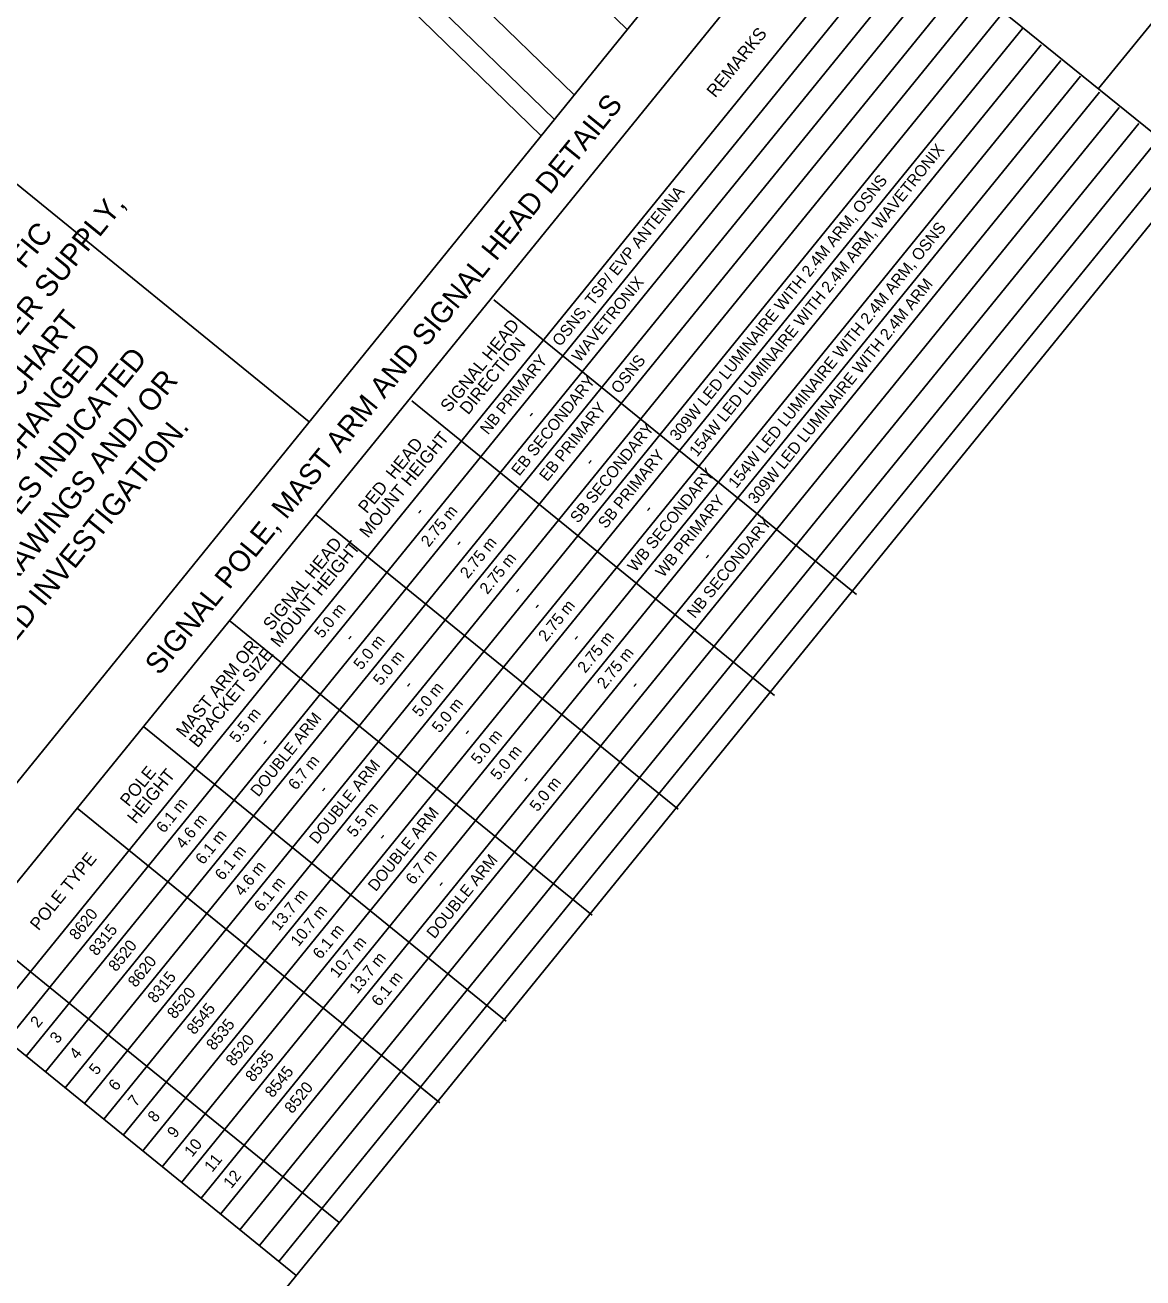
# Model space of a CAD drawing. Extents: x 592613 to 600223, y 4837996 to 4840103.
# Drawn here: x 592777.5 to 592830.8, y 4838919.8 to 4838979.6 of the extents above; entities that cross this region are included whole.
import ezdxf

# ---------------------------------------------------------------- set-up
doc = ezdxf.new("R2010")
doc.units = 0
for name, color, linetype in [('ENG_BORDER', 7, 'Continuous'), ('ENG_KILLSTRIP', 7, 'Continuous'), ('ENG_SIDEWALK', 7, 'Continuous'), ('ENG_TITLEBLOCK', 7, 'Continuous'), ('ENG_TX_TITLEBLOCK', 7, 'Continuous'), ('Level 31', 7, 'Continuous'), ('Level 54', 7, 'Continuous'), ('ROW_ENG_ROW', 7, 'Continuous')]:
    doc.layers.add(name, color=color, linetype=linetype)

msp = doc.modelspace()

# ---------------------------------------------------------------- linework, layer by layer
at = {"layer": 'ENG_BORDER'}
for p, q in [((592790.401, 4838919.927), (592686.018, 4839004.737)), ((592833.5, 4838972.733), (592813.742, 4838988.708)), ((592773.181, 4838933.919), (592816.128, 4838986.778)), ((592799.688, 4838966.543), (592799.798, 4838966.679))]:
    msp.add_line(p, q, dxfattribs=at)
msp.add_lwpolyline([(592762.862, 4838886.033), (592888.241, 4839040.345), (592783.858, 4839125.156)], dxfattribs=at)
at = {"layer": 'ENG_KILLSTRIP'}
msp.add_line((592806.215, 4838979.424), (592802.069, 4838983.452), dxfattribs=at)
at = {"layer": 'ENG_SIDEWALK'}
for p, q in [((592803.686, 4838976.304), (592781.61, 4838997.751)), ((592802.738, 4838975.135), (592780.976, 4838996.276))]:
    msp.add_line(p, q, dxfattribs=at)
at = {"layer": 'ENG_TITLEBLOCK'}
for p, q in [((592770.854, 4838935.809), (592843.567, 4839025.495)), ((592828.718, 4838976.602), (592839.517, 4838989.892)), ((592791.029, 4838960.693), (592772.408, 4838975.825))]:
    msp.add_line(p, q, dxfattribs=at)
at = {"layer": 'Level 31'}
for p, q in [((592775.654, 4838931.909), (592818.581, 4838984.742)), ((592778.657, 4838933.708), (592819.509, 4838983.988)), ((592777.511, 4838930.4), (592820.437, 4838983.234)), ((592778.439, 4838929.646), (592821.338, 4838982.446)), ((592779.367, 4838928.893), (592822.28, 4838981.709)), ((592780.295, 4838928.139), (592823.222, 4838980.971)), ((592781.222, 4838927.385), (592824.135, 4838980.201)), ((592782.15, 4838926.631), (592825.091, 4838979.48)), ((592783.079, 4838925.877), (592825.992, 4838978.692)), ((592784.007, 4838925.122), (592826.92, 4838977.939)), ((592784.935, 4838924.368), (592827.862, 4838977.201)), ((592785.863, 4838923.615), (592828.776, 4838976.43)), ((592786.791, 4838922.86), (592829.718, 4838975.694)), ((592787.719, 4838922.106), (592830.646, 4838974.939)), ((592788.648, 4838921.352), (592831.573, 4838974.186)), ((592789.575, 4838920.598), (592832.502, 4838973.431)), ((592817.174, 4838952.449), (592799.851, 4838966.523)), ((592813.248, 4838947.618), (592795.926, 4838961.692)), ((592808.656, 4838942.186), (592791.333, 4838956.26)), ((592787.26, 4838951.169), (592787.222, 4838951.2)), ((592804.545, 4838937.126), (592787.26, 4838951.169)), ((592783.126, 4838946.129), (592783.111, 4838946.141)), ((592800.433, 4838932.066), (592783.126, 4838946.129)), ((592797.271, 4838928.174), (592779.949, 4838942.248)), ((592776.582, 4838931.155), (592778.604, 4838933.643))]:
    msp.add_line(p, q, dxfattribs=at)
at = {"layer": 'Level 54'}
for p, q in [((592797.169, 4838928.257), (592779.949, 4838942.248)), ((592777.701, 4838934.439), (592775.233, 4838936.445)), ((592777.706, 4838934.435), (592777.701, 4838934.439)), ((592778.634, 4838933.681), (592777.706, 4838934.435)), ((592792.453, 4838922.453), (592778.634, 4838933.681))]:
    msp.add_line(p, q, dxfattribs=at)
at = {"layer": 'ROW_ENG_ROW'}
msp.add_line((592802.105, 4838974.355), (592787.344, 4838988.695), dxfattribs=at)

# ---------------------------------------------------------------- texts
at = {"layer": 'ENG_TX_TITLEBLOCK'}
for s, height, rotation, p in [('REMARKS', 0.6, 50.9062, (592810.42, 4838976.135)), ('SIGNAL POLE, MAST ARM AND SIGNAL HEAD DETAILS', 1, 50.9062, (592783.878, 4838948.543)), ('154W LED LUMINAIRE WITH 2.4M ARM, WAVETRONIX', 0.55, 51.14583, (592809.555, 4838958.983)), ('309W LED LUMINAIRE WITH 2.4M ARM, OSNS', 0.55, 51.14583, (592808.62, 4838959.736)), ('OSNS, TSP/ EVP ANTENNA', 0.55, 51.14583, (592803.013, 4838964.253)), ('CONTROLLER, TRANSFORMER, POWER SUPPLY, ', 1.03687, 50.90123, (592761.365, 4838945.304)), ('CHAMBERS, STREET LIGHTING, TRAFFIC ', 1.03687, 50.90123, (592761.396, 4838948.218)), ('154W LED LUMINAIRE WITH 2.4M ARM, OSNS', 0.55, 51.14583, (592811.424, 4838957.477)), ('WAVETRONIX', 0.55, 51.14583, (592803.948, 4838963.5)), ('309W LED LUMINAIRE WITH 2.4M ARM', 0.55, 51.14583, (592812.358, 4838956.725)), ('AND SIGNAL HEAD DETAILS CHART ', 1.03687, 50.90123, (592764.988, 4838946.884)), ('SIGNAL HEAD', 0.6, 50.9062, (592797.703, 4838961.106)), ('DIRECTION', 0.6, 50.9062, (592798.621, 4838960.99)), ('INFORMATION IS TO BE CHANGED ', 1.03687, 50.90123, (592766.49, 4838945.855)), ('BASED ON ANY CHANGES INDICATED ', 1.03687, 50.90123, (592767.255, 4838943.919)), ('NB PRIMARY', 0.55, 51.14583, (592799.567, 4838960.041)), ('OSNS', 0.55, 51.14583, (592805.817, 4838961.994)), ('ON THE REDLINE DRAWINGS AND/ OR', 1.03687, 50.90123, (592768.536, 4838942.618)), ('EB SECONDARY', 0.55, 51.14583, (592801.061, 4838958.069)), ('EB PRIMARY', 0.55, 51.14583, (592802.393, 4838957.81)), ('-', 0.55, 51.14583, (592801.725, 4838960.807)), (' DURING A FIELD INVESTIGATION.', 1.03687, 50.90123, (592770.867, 4838942.61)), ('SB SECONDARY', 0.55, 51.14583, (592803.864, 4838955.811)), ('PED  HEAD', 0.6, 50.9062, (592793.778, 4838956.275)), ('MOUNT HEIGHT', 0.6, 50.9062, (592793.839, 4838955.105)), ('SB PRIMARY', 0.55, 51.14583, (592805.196, 4838955.552)), ('-', 0.55, 51.14583, (592804.529, 4838958.549)), ('WB SECONDARY', 0.55, 51.14583, (592806.61, 4838953.482)), ('WB PRIMARY', 0.55, 51.14583, (592807.943, 4838953.223)), ('-', 0.55, 51.14583, (592796.401, 4838956.171)), ('2.75 m', 0.55, 51.14583, (592796.738, 4838954.676)), ('-', 0.55, 51.14583, (592807.332, 4838956.291)), ('NB SECONDARY', 0.55, 51.14583, (592809.449, 4838951.267)), ('SIGNAL HEAD', 0.6, 50.9062, (592789.235, 4838950.683)), ('MOUNT HEIGHT', 0.6, 50.9062, (592789.591, 4838949.877)), ('-', 0.55, 51.14583, (592798.27, 4838954.665)), ('2.75 m', 0.55, 51.14583, (592798.607, 4838953.17)), ('2.75 m', 0.55, 51.14583, (592799.541, 4838952.417)), ('-', 0.55, 51.14583, (592810.136, 4838954.032)), ('-', 0.55, 51.14583, (592801.074, 4838952.407)), ('2.75 m', 0.55, 51.14583, (592802.345, 4838950.159)), ('5.0 m', 0.55, 51.14583, (592791.652, 4838950.316)), ('-', 0.55, 51.14583, (592802.008, 4838951.654)), ('MAST ARM OR', 0.6, 50.9062, (592785.081, 4838945.571)), ('-', 0.55, 51.14583, (592793.064, 4838950.156)), ('5.0 m', 0.55, 51.14583, (592793.521, 4838948.81)), ('-', 0.55, 51.14583, (592803.877, 4838950.148)), ('2.75 m', 0.55, 51.14583, (592804.214, 4838948.653)), ('BRACKET SIZE', 0.6, 50.9062, (592785.701, 4838945.089)), ('5.0 m', 0.55, 51.14583, (592794.456, 4838948.057)), ('2.75 m', 0.55, 51.14583, (592805.148, 4838947.9)), ('-', 0.55, 51.14583, (592795.868, 4838947.897)), ('5.0 m', 0.55, 51.14583, (592796.325, 4838946.552)), ('-', 0.55, 51.14583, (592806.681, 4838947.89)), ('5.0 m', 0.55, 51.14583, (592797.259, 4838945.799)), ('5.5 m', 0.55, 51.14583, (592787.597, 4838945.325)), ('DOUBLE ARM', 0.55, 51.14583, (592788.602, 4838942.746)), ('-', 0.55, 51.14583, (592789.009, 4838945.165)), ('-', 0.55, 51.14583, (592798.671, 4838945.639)), ('5.0 m', 0.55, 51.14583, (592799.128, 4838944.293)), ('5.0 m', 0.55, 51.14583, (592800.063, 4838943.54)), ('POLE', 0.6, 50.9062, (592782.405, 4838942.278)), ('6.7 m', 0.55, 51.14583, (592790.4, 4838943.066)), ('DOUBLE ARM', 0.55, 51.14583, (592791.405, 4838940.488)), ('HEIGHT', 0.6, 50.9062, (592782.75, 4838941.457)), ('-', 0.55, 51.14583, (592801.475, 4838943.381)), ('5.0 m', 0.55, 51.14583, (592801.932, 4838942.035)), ('-', 0.55, 51.14583, (592791.812, 4838942.906)), ('6.1 m', 0.55, 51.14583, (592784.096, 4838941.015)), ('5.5 m', 0.55, 51.14583, (592793.204, 4838940.808)), ('4.6 m', 0.55, 51.14583, (592785.03, 4838940.263)), ('DOUBLE ARM', 0.55, 51.14583, (592794.209, 4838938.229)), ('6.1 m', 0.55, 51.14583, (592785.965, 4838939.51)), ('-', 0.55, 51.14583, (592794.616, 4838940.648)), ('POLE TYPE', 0.6, 50.9062, (592778.102, 4838936.359)), ('6.1 m', 0.55, 51.14583, (592786.899, 4838938.757)), ('6.7 m', 0.55, 51.14583, (592796.007, 4838938.549)), ('DOUBLE ARM', 0.55, 51.14583, (592797.012, 4838935.971)), ('4.6 m', 0.55, 51.14583, (592787.834, 4838938.004)), ('6.1 m', 0.55, 51.14583, (592788.768, 4838937.251)), ('13.7 m', 0.55, 51.14583, (592789.582, 4838936.349)), ('-', 0.55, 51.14583, (592797.419, 4838938.389)), ('8620', 0.55, 51.14583, (592779.94, 4838935.902)), ('10.7 m', 0.55, 51.14583, (592790.517, 4838935.596)), ('8315', 0.55, 51.14583, (592780.876, 4838935.151)), ('6.1 m', 0.55, 51.14583, (592791.572, 4838934.993)), ('8520', 0.55, 51.14583, (592781.809, 4838934.397)), ('10.7 m', 0.55, 51.14583, (592792.386, 4838934.091)), ('13.7 m', 0.55, 51.14583, (592793.32, 4838933.338)), ('8620', 0.55, 51.14583, (592782.744, 4838933.644)), ('8315', 0.55, 51.14583, (592783.68, 4838932.893)), ('6.1 m', 0.55, 51.14583, (592794.375, 4838932.735)), ('8520', 0.55, 51.14583, (592784.613, 4838932.138)), ('8545', 0.55, 51.14583, (592785.549, 4838931.387)), ('2', 0.55, 51.14583, (592778.081, 4838931.719)), ('8535', 0.55, 51.14583, (592786.483, 4838930.634)), ('3', 0.55, 51.14583, (592779.015, 4838930.966)), ('8520', 0.55, 51.14583, (592787.416, 4838929.88)), ('4', 0.55, 51.14583, (592779.947, 4838930.21)), ('8535', 0.55, 51.14583, (592788.352, 4838929.129)), ('5', 0.55, 51.14583, (592780.884, 4838929.46)), ('8545', 0.55, 51.14583, (592789.287, 4838928.376)), ('6', 0.55, 51.14583, (592781.816, 4838928.704)), ('8520', 0.55, 51.14583, (592790.22, 4838927.621)), ('7', 0.55, 51.14583, (592782.746, 4838927.946)), ('8', 0.55, 51.14583, (592783.686, 4838927.2)), ('9', 0.55, 51.14583, (592784.622, 4838926.449)), ('10', 0.55, 51.14583, (592785.434, 4838925.545)), ('11', 0.55, 51.14583, (592786.393, 4838924.822)), ('12', 0.55, 51.14583, (592787.305, 4838924.042))]:
    msp.add_text(s, height=height, rotation=rotation, dxfattribs=at).set_placement(p)

doc.saveas('drawing.dxf')
